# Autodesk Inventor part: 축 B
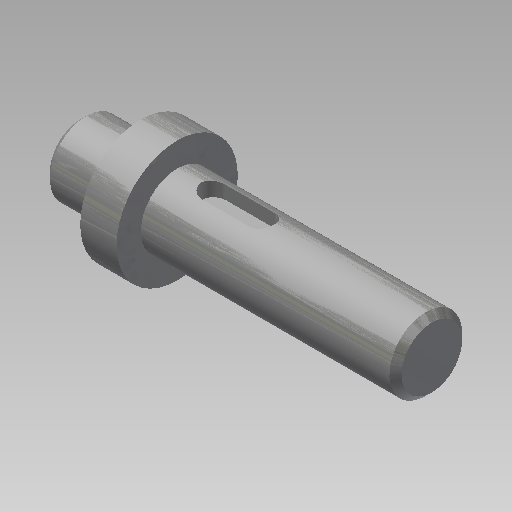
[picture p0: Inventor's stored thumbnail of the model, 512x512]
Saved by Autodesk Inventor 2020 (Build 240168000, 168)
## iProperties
Created: 2020-04
Part Number: 축 B
Material: 강철, 연강
Document SubType Name: Modeling
Designer: mduedu
Density: 7.86 g/cm^3
Mass: 59.9336 g
Surface Area: 29.7709 cm^2
Volume: 7.62514 cm^3
Appearance: 강철
Author: mduedu
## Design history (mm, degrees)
revolve "회전1" stored, may be unused: angle "d11" = 90 deg
sketch "스케치3"
  geometry: L1 (0, -6)-(0, 6) reference; L2 (0, 6)-(10, 6) reference; L3 (10, 6)-(10, 10) reference; L4 (10, 10)-(16, 10) reference; L5 (16, 10)-(16, 6) reference; L6 (16, 6)-(58, 6) reference; L7 (58, 6)-(58, -6) reference; L8 (58, -6)-(16, -6) reference; L9 (16, -6)-(16, -10) reference; L10 (16, -10)-(10, -10) reference; L11 (10, -10)-(10, -6) reference; L12 (10, -6)-(0, -6) reference; L13 (20, 6)-(32, 6); L14 (32, 6)-(32, 3.5); L15 (32, 3.5)-(20, 3.5); L16 (20, 3.5)-(20, 6); 1 further point
  constraints: 8 end point, 2 parallel, 1 horizontal, 1 perpendicular, 1 point on line
  dimensions: "d17" = 12 distance of L14.end L15.end; "d18" = 2.5 distance of L13.end L14.end; "d19" = 4 distance from line of L16 L4.end
extrude "돌출2" cut sketch "스케치3" stored distance "d20" = 4; taper "d21" = 0 deg
fillet "모깎기2" dims "d22" = 2
chamfer "모따기1" distance "d23" = 1; stored, may be unused: second distance "d24" = 2, angle "d25" = 45 deg
chamfer "모따기2" distance "d26" = 1; stored, may be unused: second distance "d27" = 2, angle "d28" = 45 deg
fillet "모깎기3" dims "d29" = 0.3
node "솔리드1"
sketch "스케치1"
  geometry: L1 (0, 0)-(10, 0); L2 (10, 0)-(10, 6); L3 (10, 6)-(0, 6); L4 (0, 6)-(0, 0); L5 (10, 0)-(16, 0); L6 (16, 0)-(16, 10); L7 (16, 10)-(10, 10); L8 (10, 10)-(10, 0); L9 (16, 0)-(58, 0); L10 (58, 0)-(58, 6); L11 (58, 6)-(16, 6); L12 (16, 6)-(16, 0); L13 (58, 0)-(58, 0); L14 (58, 5)-(58, 0)
  constraints: 28 end point, 6 parallel, 4 horizontal, 3 perpendicular
  dimensions: "d2" = 10 distance of L2.end L3.end; "d3" = 6 distance of L6.end L7.end; "d7" = 12 diameter of L11 L9; "d8" = 12 diameter of L3 L1; "d9" = 20 diameter of L7 L5; "d36" = 58 distance between parallel lines of L10 L4
node "절단 모서리 투영2"
